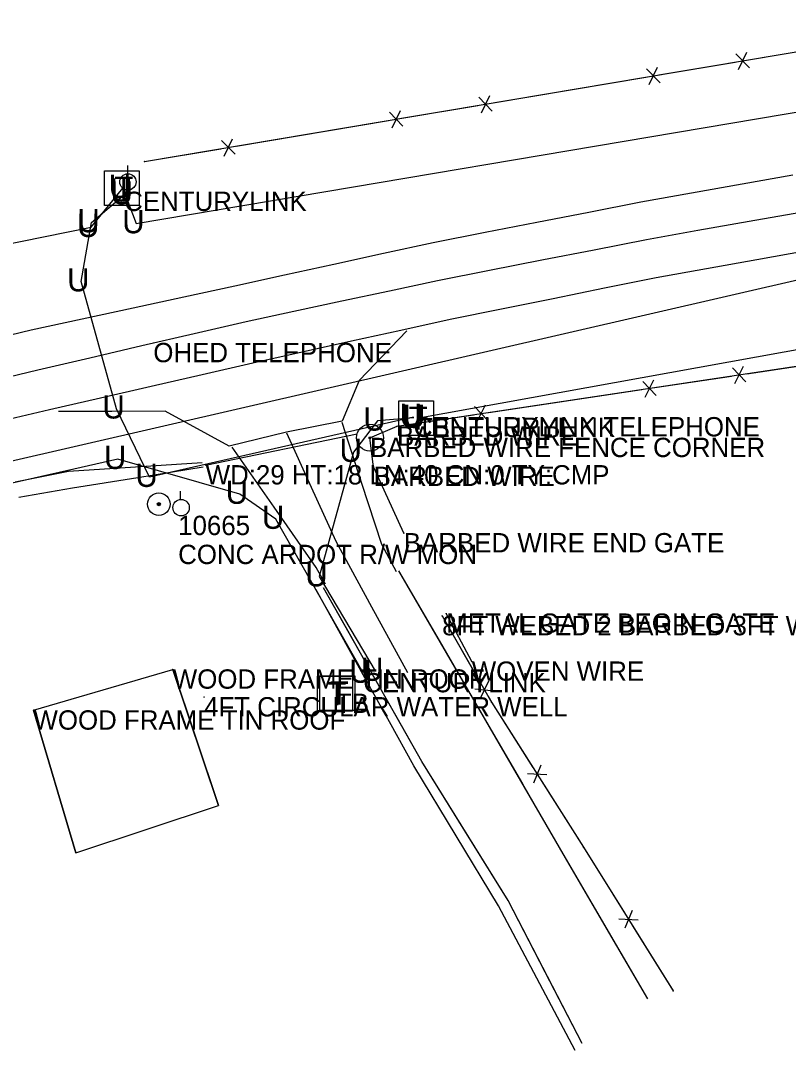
# Model space of a CAD drawing. Extents: x 1568433 to 1572450, y 731863 to 733450.
# Drawn here: x 1569616 to 1569814.5, y 731936.3 to 732202.6 of the extents above; entities that cross this region are included whole.
import ezdxf

# ---------------------------------------------------------------- set-up
doc = ezdxf.new("R2010")
doc.units = 0
for name, color, linetype in [('Default', 7, 'Continuous'), ('S_BASELINE', 7, 'Continuous'), ('S_BUILDING', 7, 'Continuous'), ('S_BUILDING_ANNOT', 7, 'Continuous'), ('S_CROSS_DRAIN_ANNOT', 7, 'Continuous'), ('S_DITCHLINE', 7, 'Continuous'), ('S_DRG_PT_SYM', 7, 'Continuous'), ('S_EDGE_BITUMINOUS', 7, 'Continuous'), ('S_EDGE_PAVEMENT', 7, 'Continuous'), ('S_FENCE', 7, 'Continuous'), ('S_FENCE_ANNOT', 7, 'Continuous'), ('S_GRAVEL_ROAD', 7, 'Continuous'), ('S_IRON_PIN', 7, 'Continuous'), ('S_IRON_PIN_ANNOT', 7, 'Continuous'), ('S_MISC_STRUCTURES_ANNOT', 7, 'Continuous'), ('S_MSC_PT_SYM', 7, 'Continuous'), ('S_PAVEMENT_CROWN', 7, 'Continuous'), ('S_SIDE_DRAIN', 7, 'Continuous'), ('S_SURVEY_TEXT_ANNOT', 7, 'Continuous'), ('S_TELEPHONE_UTILITIES', 7, 'Continuous'), ('S_TELEPHONE_UTILITIES_ANNOT', 7, 'Continuous'), ('S_UNDERGROUND_CABLE', 7, 'Continuous'), ('S_UNDERGROUND_CABLE_ANNOT', 7, 'Continuous'), ('S_UTILITY_POLE', 7, 'Continuous')]:
    doc.layers.add(name, color=color, linetype=linetype)

msp = doc.modelspace()

# ---------------------------------------------------------------- linework, layer by layer
at = {"layer": 'S_BASELINE'}
msp.add_line((1569114.63, 731973.54), (1569838.9, 732140.65), dxfattribs=at)
at = {"layer": 'S_BUILDING'}
for p, q in [((1569619.36, 732024.21), (1569655.38, 732034.8)), ((1569630.29, 731987.35), (1569667.23, 731999.56))]:
    msp.add_line(p, q, dxfattribs=at)
for points in [[(1569655.38, 732034.8), (1569655.38, 732034.85), (1569667.23, 731999.56), (1569655.38, 732034.8), (1569655.33, 732034.8), (1569655.38, 732034.8), (1569655.38, 732034.75), (1569655.38, 732034.8), (1569655.43, 732034.8)], [(1569619.36, 732024.21), (1569619.36, 732024.26), (1569630.29, 731987.35), (1569619.36, 732024.21), (1569619.31, 732024.21), (1569619.36, 732024.21), (1569619.36, 732024.16), (1569619.36, 732024.21), (1569619.41, 732024.21)]]:
    msp.add_lwpolyline(points, dxfattribs=at)
at = {"layer": 'S_DITCHLINE'}
for points in [[(1569614.65, 732083.28), (1569628.41, 732086.06), (1569645.71, 732087.19), (1569663.01, 732088.32)], [(1569615.54, 732079.3), (1569629.42, 732081.72), (1569646.33, 732084.43), (1569663.25, 732087.14)], [(1569759.38, 731936.26), (1569749.46, 731954.94), (1569739.54, 731973.63), (1569728.61, 731991.74), (1569717.68, 732009.85), (1569711.37, 732021.23), (1569705.06, 732032.62), (1569698.75, 732044), (1569692.44, 732055.39)]]:
    msp.add_lwpolyline(points, dxfattribs=at)
at = {"layer": 'S_DRG_PT_SYM'}
msp.add_lwpolyline([(1569663.87, 732087.62), (1569663.87, 732087.67), (1569663.87, 732087.62), (1569663.82, 732087.62), (1569663.87, 732087.62), (1569663.87, 732087.57), (1569663.87, 732087.62), (1569663.92, 732087.62)], dxfattribs=at)
at = {"layer": 'S_EDGE_BITUMINOUS'}
msp.add_lwpolyline([(1569715.87, 732122.38), (1569703.56, 732109.49), (1569699.17, 732098.99), (1569684.75, 732096.16), (1569669.91, 732092.56), (1569653.42, 732101.57), (1569639.61, 732101.53), (1569625.8, 732101.49)], dxfattribs=at)
at = {"layer": 'S_EDGE_PAVEMENT'}
for points in [[(1569605.47, 732119.41), (1569618.77, 732122.62), (1569631.94, 732125.46), (1569645.1, 732128.3), (1569658.27, 732131.14), (1569671.43, 732133.99), (1569684.24, 732136.79), (1569697.05, 732139.6), (1569709.87, 732142.41), (1569722.68, 732145.21), (1569736.1, 732147.83), (1569749.51, 732150.45), (1569762.93, 732153.07), (1569776.35, 732155.68), (1569789.47, 732158.02), (1569802.59, 732160.35), (1569815.71, 732162.68)], [(1569610.25, 732098.87), (1569623.54, 732102.04), (1569636.67, 732105.06), (1569649.8, 732108.07), (1569662.93, 732111.09), (1569676.06, 732114.11), (1569688.81, 732116.92), (1569701.56, 732119.73), (1569714.3, 732122.54), (1569727.05, 732125.35), (1569740.37, 732128.05), (1569753.69, 732130.75), (1569767.01, 732133.45), (1569780.33, 732136.14), (1569793.33, 732138.48), (1569806.33, 732140.81), (1569819.33, 732143.14)]]:
    msp.add_lwpolyline(points, dxfattribs=at)
at = {"layer": 'S_FENCE'}
for p, q in [((1569648.06, 732166.13), (1569864.46, 732202.58)), ((1569800.96, 732193.96), (1569804.47, 732190.4)), ((1569800.96, 732193.96), (1569804.47, 732190.4)), ((1569801.64, 732189.92), (1569803.79, 732194.44)), ((1569801.64, 732189.92), (1569803.79, 732194.44)), ((1569777.86, 732190.07), (1569781.36, 732186.51)), ((1569777.86, 732190.07), (1569781.36, 732186.51)), ((1569778.54, 732186.03), (1569780.68, 732190.55)), ((1569778.54, 732186.03), (1569780.68, 732190.55)), ((1569734.48, 732182.76), (1569737.98, 732179.2)), ((1569734.48, 732182.76), (1569737.98, 732179.2)), ((1569735.16, 732178.72), (1569737.3, 732183.24)), ((1569735.16, 732178.72), (1569737.3, 732183.24)), ((1569711.37, 732178.87), (1569714.88, 732175.31)), ((1569711.37, 732178.87), (1569714.88, 732175.31)), ((1569712.05, 732174.83), (1569714.2, 732179.35)), ((1569712.05, 732174.83), (1569714.2, 732179.35)), ((1569667.99, 732171.56), (1569671.5, 732168)), ((1569667.99, 732171.56), (1569671.5, 732168)), ((1569668.67, 732167.52), (1569670.82, 732172.04)), ((1569668.67, 732167.52), (1569670.82, 732172.04)), ((1569713.34, 732097.66), (1569896.24, 732125.16)), ((1569800.05, 732112.77), (1569803.5, 732109.14)), ((1569800.05, 732112.77), (1569803.5, 732109.14)), ((1569800.66, 732108.72), (1569802.89, 732113.19)), ((1569800.66, 732108.72), (1569802.89, 732113.19)), ((1569776.88, 732109.28), (1569780.33, 732105.66)), ((1569776.88, 732109.28), (1569780.33, 732105.66)), ((1569777.49, 732105.23), (1569779.72, 732109.71)), ((1569777.49, 732105.23), (1569779.72, 732109.71)), ((1569733.37, 732102.74), (1569736.82, 732099.12)), ((1569733.37, 732102.74), (1569736.82, 732099.12)), ((1569733.98, 732098.69), (1569736.21, 732103.17)), ((1569733.98, 732098.69), (1569736.21, 732103.17)), ((1569706.35, 732094.7), (1569713.34, 732097.66)), ((1569707.3, 732087.22), (1569706.35, 732094.7)), ((1569715.1, 732070.05), (1569707.3, 732087.22)), ((1569725.02, 732048.61), (1569737.77, 732026.3)), ((1569732.66, 732036.84), (1569726.06, 732049.26)), ((1569737, 732031.77), (1569734.87, 732027.25)), ((1569733.45, 732029.74), (1569738.43, 732029.28)), ((1569737.77, 732026.3), (1569761.55, 731988.8)), ((1569747.05, 732007.84), (1569752.05, 732007.61)), ((1569750.51, 732010.03), (1569748.59, 732005.41)), ((1569761.55, 731988.8), (1569784.73, 731951.65)), ((1569770.7, 731970.27), (1569775.69, 731970)), ((1569774.17, 731972.44), (1569772.22, 731967.84))]:
    msp.add_line(p, q, dxfattribs=at)
for points in [[(1569804.69, 732192.51), (1569844.12, 732199.16)], [(1569804.69, 732192.51), (1569844.12, 732199.16)], [(1569781.02, 732188.53), (1569800.74, 732191.85)], [(1569781.02, 732188.53), (1569800.74, 732191.85)], [(1569738.2, 732181.31), (1569777.64, 732187.96)], [(1569738.2, 732181.31), (1569777.64, 732187.96)], [(1569714.54, 732177.33), (1569734.26, 732180.65)], [(1569714.54, 732177.33), (1569734.26, 732180.65)], [(1569671.72, 732170.11), (1569711.15, 732176.76)], [(1569671.72, 732170.11), (1569711.15, 732176.76)], [(1569648.06, 732166.13), (1569667.77, 732169.45)], [(1569648.06, 732166.13), (1569667.77, 732169.45)], [(1569803.75, 732111.25), (1569843.3, 732117.2)], [(1569803.75, 732111.25), (1569843.3, 732117.2)], [(1569780.02, 732107.68), (1569799.8, 732110.66)], [(1569780.02, 732107.68), (1569799.8, 732110.66)], [(1569737.07, 732101.23), (1569776.63, 732107.17)], [(1569737.07, 732101.23), (1569776.63, 732107.17)], [(1569713.34, 732097.66), (1569733.12, 732100.63)], [(1569713.34, 732097.66), (1569733.12, 732100.63)], [(1569706.35, 732094.7), (1569713.34, 732097.66)], [(1569706.35, 732094.7), (1569713.34, 732097.66)], [(1569707.3, 732087.22), (1569706.35, 732094.7)], [(1569707.3, 732087.22), (1569706.35, 732094.7)], [(1569715.1, 732070.05), (1569707.3, 732087.22)], [(1569715.1, 732070.05), (1569707.3, 732087.22)], [(1569725.02, 732048.61), (1569734.95, 732031.24)], [(1569736.93, 732027.77), (1569737.77, 732026.3)], [(1569737.77, 732026.3), (1569748.48, 732009.41)], [(1569750.62, 732006.03), (1569761.55, 731988.8)], [(1569761.55, 731988.8), (1569772.14, 731971.83)], [(1569774.25, 731968.44), (1569784.73, 731951.65)]]:
    msp.add_lwpolyline(points, dxfattribs=at)
for radius in [3.49, 0.247, 0.0349]:
    msp.add_circle((1569706.35, 732094.7), radius, dxfattribs=at)
at = {"layer": 'S_GRAVEL_ROAD'}
for p, q in [((1569713.76, 732060.26), (1569734.7, 732024.22)), ((1569719.72, 732011.01), (1569694.34, 732055.9)), ((1569734.7, 732024.22), (1569756.8, 731986.1)), ((1569742.11, 731975.03), (1569719.72, 732011.01)), ((1569756.8, 731986.1), (1569778.07, 731949.62)), ((1569761.17, 731938.04), (1569742.11, 731975.03))]:
    msp.add_line(p, q, dxfattribs=at)
for points in [[(1569699.09, 732098.69), (1569704.2, 732082.94), (1569709.3, 732067.19), (1569713.1, 732060.12)], [(1569694.85, 732056.82), (1569692.48, 732061.16), (1569681.59, 732076.72), (1569670.7, 732092.28)], [(1569713.76, 732060.26), (1569724.23, 732042.24), (1569734.7, 732024.22), (1569745.75, 732005.16), (1569756.8, 731986.1), (1569767.43, 731967.86), (1569778.07, 731949.62)], [(1569761.17, 731938.04), (1569751.64, 731956.53), (1569742.11, 731975.03), (1569730.91, 731993.02), (1569719.72, 732011.01), (1569713.38, 732022.24), (1569707.03, 732033.46), (1569700.69, 732044.68), (1569694.34, 732055.9)]]:
    msp.add_lwpolyline(points, dxfattribs=at)
at = {"layer": 'S_IRON_PIN'}
for radius in [2.91, 0.411, 0.262, 0.212, 0.145, 0.0822, 0.0581]:
    msp.add_circle((1569651.76, 732077.53), radius, dxfattribs=at)
at = {"layer": 'S_MSC_PT_SYM'}
for points in [[(1569648.06, 732166.13), (1569648.06, 732166.18), (1569648.06, 732166.13), (1569648.01, 732166.13), (1569648.06, 732166.13), (1569648.06, 732166.08), (1569648.06, 732166.13), (1569648.11, 732166.13)], [(1569650.34, 732119.23), (1569650.34, 732119.28), (1569650.34, 732119.23), (1569650.29, 732119.23), (1569650.34, 732119.23), (1569650.34, 732119.18), (1569650.34, 732119.23), (1569650.39, 732119.23)], [(1569713.34, 732097.66), (1569713.34, 732097.71), (1569713.34, 732097.66), (1569713.29, 732097.66), (1569713.34, 732097.66), (1569713.34, 732097.61), (1569713.34, 732097.66), (1569713.39, 732097.66)], [(1569706.35, 732094.7), (1569706.35, 732094.75), (1569706.35, 732094.7), (1569706.3, 732094.7), (1569706.35, 732094.7), (1569706.35, 732094.65), (1569706.35, 732094.7), (1569706.4, 732094.7)], [(1569707.3, 732087.22), (1569707.3, 732087.27), (1569707.3, 732087.22), (1569707.25, 732087.22), (1569707.3, 732087.22), (1569707.3, 732087.17), (1569707.3, 732087.22), (1569707.35, 732087.22)], [(1569715.1, 732070.05), (1569715.1, 732070.1), (1569715.1, 732070.05), (1569715.05, 732070.05), (1569715.1, 732070.05), (1569715.1, 732070), (1569715.1, 732070.05), (1569715.15, 732070.05)], [(1569725.02, 732048.61), (1569725.02, 732048.66), (1569725.02, 732048.61), (1569724.97, 732048.61), (1569725.02, 732048.61), (1569725.02, 732048.56), (1569725.02, 732048.61), (1569725.07, 732048.61)], [(1569726.06, 732049.26), (1569726.06, 732049.31), (1569726.06, 732049.26), (1569726.01, 732049.26), (1569726.06, 732049.26), (1569726.06, 732049.21), (1569726.06, 732049.26), (1569726.11, 732049.26)], [(1569732.66, 732036.84), (1569732.66, 732036.89), (1569732.66, 732036.84), (1569732.61, 732036.84), (1569732.66, 732036.84), (1569732.66, 732036.79), (1569732.66, 732036.84), (1569732.71, 732036.84)], [(1569663.46, 732027.62), (1569663.46, 732027.67), (1569663.46, 732027.62), (1569663.41, 732027.62), (1569663.46, 732027.62), (1569663.46, 732027.57), (1569663.46, 732027.62), (1569663.51, 732027.62)], [(1569737.77, 732026.3), (1569737.77, 732026.35), (1569737.77, 732026.3), (1569737.72, 732026.3), (1569737.77, 732026.3), (1569737.77, 732026.25), (1569737.77, 732026.3), (1569737.82, 732026.3)], [(1569761.55, 731988.8), (1569761.55, 731988.85), (1569761.55, 731988.8), (1569761.5, 731988.8), (1569761.55, 731988.8), (1569761.55, 731988.75), (1569761.55, 731988.8), (1569761.6, 731988.8)], [(1569784.73, 731951.65), (1569784.73, 731951.7), (1569784.73, 731951.65), (1569784.68, 731951.65), (1569784.73, 731951.65), (1569784.73, 731951.6), (1569784.73, 731951.65), (1569784.78, 731951.65)]]:
    msp.add_lwpolyline(points, dxfattribs=at)
at = {"layer": 'S_PAVEMENT_CROWN'}
for points in [[(1569607.52, 732109.12), (1569620.49, 732112.26), (1569633.95, 732115.39), (1569647.41, 732118.52), (1569660.88, 732121.65), (1569674.34, 732124.78), (1569686.7, 732127.43), (1569699.06, 732130.08), (1569711.42, 732132.73), (1569723.78, 732135.38), (1569737.28, 732138.03), (1569750.79, 732140.68), (1569764.3, 732143.33), (1569777.81, 732145.98), (1569791.11, 732148.35), (1569804.41, 732150.72), (1569817.71, 732153.08)], [(1569684.81, 732095.95), (1569691.16, 732081.95), (1569697.5, 732067.95), (1569706.77, 732050.95), (1569716.04, 732033.95)]]:
    msp.add_lwpolyline(points, dxfattribs=at)
at = {"layer": 'S_SIDE_DRAIN'}
msp.add_line((1569663.87, 732087.62), (1569703.04, 732095.69), dxfattribs=at)
at = {"layer": 'S_TELEPHONE_UTILITIES'}
for points in [[(1569637.71, 732154.74), (1569637.71, 732163.74), (1569646.71, 732163.74), (1569646.71, 732154.74)], [(1569713.78, 732095.28), (1569713.78, 732104.28), (1569722.78, 732104.28), (1569722.78, 732095.28)], [(1569692.82, 732024.01), (1569692.82, 732033.01), (1569701.82, 732033.01), (1569701.82, 732024.01)], [(1569693.42, 732024.17), (1569693.42, 732033.17), (1569702.42, 732033.17), (1569702.42, 732024.17)]]:
    msp.add_lwpolyline(points, close=True, dxfattribs=at)
at = {"layer": 'S_UNDERGROUND_CABLE'}
for p, q in [((1569645.93, 732150.12), (1569839.84, 732182.82)), ((1569634.25, 732149.16), (1569642.44, 732159.26)), ((1569634.34, 732150.37), (1569642.9, 732157.59)), ((1569642.8, 732158.34), (1569645.93, 732150.12)), ((1569569.32, 732136.1), (1569634.25, 732149.16)), ((1569631.68, 732135.09), (1569634.34, 732150.37)), ((1569640.81, 732102.21), (1569631.68, 732135.09)), ((1569718.51, 732099.8), (1569879.8, 732128.85)), ((1569649.34, 732084.54), (1569640.81, 732102.21)), ((1569717.62, 732100.04), (1569649.34, 732084.54)), ((1569708.27, 732099.08), (1569702.11, 732091)), ((1569717.72, 732099.88), (1569708.27, 732099.08)), ((1569702.11, 732091), (1569693.25, 732058.81)), ((1569641.2, 732089.16), (1569552.71, 732069.09)), ((1569672.67, 732080.15), (1569641.2, 732089.16)), ((1569682.04, 732073.68), (1569672.67, 732080.15)), ((1569704.63, 732033.87), (1569682.04, 732073.68)), ((1569693.25, 732058.81), (1569707.67, 732034.38))]:
    msp.add_line(p, q, dxfattribs=at)
at = {"layer": 'S_UTILITY_POLE'}
for p, q in [((1569643.75, 732162.95), (1569643.75, 732165.08)), ((1569643.75, 732158.73), (1569643.75, 732156.68)), ((1569657.4, 732078.77), (1569657.4, 732080.88))]:
    msp.add_line(p, q, dxfattribs=at)
for centre, radius in [((1569643.77, 732160.87), 2.11), ((1569657.52, 732076.63), 2.13)]:
    msp.add_circle(centre, radius, dxfattribs=at)

# ---------------------------------------------------------------- texts
at = {"layer": 'Default'}
for p in [(1569638.81, 732156.72), (1569639.17, 732155.79), (1569639.27, 732155.05), (1569630.62, 732146.61), (1569630.71, 732147.83), (1569642.3, 732147.58), (1569628.05, 732132.55), (1569637.18, 732099.67), (1569713.99, 732097.5), (1569704.64, 732096.54), (1569714.09, 732097.33), (1569714.88, 732097.25), (1569698.48, 732088.45), (1569637.57, 732086.62), (1569645.71, 732081.99), (1569669.05, 732077.61), (1569678.41, 732071.14), (1569689.62, 732056.26), (1569701, 732031.33), (1569704.04, 732031.83)]:
    msp.add_text('U', height=6, dxfattribs=at).set_placement(p)
at = {"layer": 'S_BUILDING_ANNOT'}
for p in [(1569655.38, 732029.8), (1569619.36, 732019.21)]:
    msp.add_text('WOOD FRAME TIN ROOF', height=5, dxfattribs=at).set_placement(p)
at = {"layer": 'S_CROSS_DRAIN_ANNOT'}
msp.add_text('WD:29 HT:18 LN:40 CN:0 TY:CMP', height=5, dxfattribs=at).set_placement((1569663.87, 732082.62))
at = {"layer": 'S_FENCE_ANNOT'}
for s, p in [('BARBED WIRE', (1569713.34, 732092.66)), ('BARBED WIRE FENCE CORNER', (1569706.35, 732089.7)), ('BARBED WIRE FENCE CORNER', (1569706.35, 732089.7)), ('BARBED WIRE', (1569707.3, 732082.22)), ('BARBED WIRE END GATE', (1569715.1, 732065.05)), ('8FT WEBED 2 BARBED 3FT WEBED 2 ', (1569725.02, 732043.61)), ('METAL GATE BEGIN GATE', (1569726.06, 732044.26)), ('WOVEN WIRE', (1569732.66, 732031.84))]:
    msp.add_text(s, height=5, dxfattribs=at).set_placement(p)
at = {"layer": 'S_IRON_PIN_ANNOT'}
for s, p in [('10665', (1569656.76, 732069.53)), ('CONC ARDOT R/W MON', (1569656.76, 732062.03))]:
    msp.add_text(s, height=5, dxfattribs=at).set_placement(p)
at = {"layer": 'S_MISC_STRUCTURES_ANNOT'}
msp.add_text('4FT CIRCULAR WATER WELL', height=5, dxfattribs=at).set_placement((1569663.46, 732022.62))
at = {"layer": 'S_SURVEY_TEXT_ANNOT'}
msp.add_text('OHED TELEPHONE', height=5, dxfattribs=at).set_placement((1569650.34, 732114.23))
at = {"layer": 'S_TELEPHONE_UTILITIES'}
for p in [(1569640.28, 732156.24), (1569716.35, 732096.78), (1569695.39, 732025.51)]:
    msp.add_text('T', height=6, dxfattribs=at).set_placement(p)
msp.add_text('T', height=6, rotation=360, dxfattribs=at).set_placement((1569695.98, 732025.67))
at = {"layer": 'S_TELEPHONE_UTILITIES_ANNOT'}
for p in [(1569718.51, 732094.8), (1569697.55, 732023.53)]:
    msp.add_text('TB', height=5, dxfattribs=at).set_placement(p)
at = {"layer": 'S_UNDERGROUND_CABLE_ANNOT'}
for s, p in [('CENTURYLINK', (1569642.8, 732153.34)), ('CENTURYLINK TELEPHONE', (1569717.62, 732095.04)), ('CENTUURYLINK', (1569717.72, 732094.88)), ('TB', (1569718.51, 732094.8)), ('CENTURYLINK', (1569704.63, 732028.87))]:
    msp.add_text(s, height=5, dxfattribs=at).set_placement(p)

doc.saveas('drawing.dxf')
